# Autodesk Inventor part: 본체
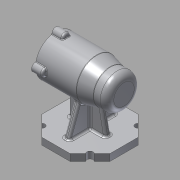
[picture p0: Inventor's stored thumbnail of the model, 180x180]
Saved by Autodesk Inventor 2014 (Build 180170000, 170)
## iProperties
Created: 2021-01
Part Number: 본체
Material: Aluminum 6061
Document SubType Name: Modeling
Designer: kh
Mass: 632.295 g
Surface Area: 613.777 cm^2
Volume: 233.319 cm^3
Density: 2.71 g/cm^3
Appearance: Aluminum - Flat
Author: kh
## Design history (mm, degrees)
sketch "Sketch1"
  geometry: L1 (20.711, 50)-(50, 20.711); L2 (50, 20.711)-(50, -20.711); L3 (50, -20.711)-(20.711, -50); L4 (20.711, -50)-(-20.711, -50); L5 (-20.711, -50)-(-50, -20.711); L6 (-50, -20.711)-(-50, 20.711); L7 (-50, 20.711)-(-20.711, 50); L8 (-20.711, 50)-(20.711, 50); L9 (0, 0)-(-35.355, 35.355); L10 (0, 0)-(-35.609, 0); L11 (0, 0)-(0, 25.422); C1 r 4.5 at (-35.355, 35.355); C2 r 4.5 at (35.355, 35.355); C3 r 4.5 at (-35.355, -35.355); C4 r 4.5 at (35.355, -35.355); A1 r 50 centre (0, 0) between (0, 50) and (-35.355, 35.355); 2 further points
  constraints: 22 end point, 5 centre point, 3 coincident, 3 midpoint, 3 symmetric about line, 2 point on circle, 1 horizontal alignment, 1 parallel, 1 perpendicular, 20 other
  dimensions: "d0" = 100 diameter of A1; "d1" = 9 diameter of C1
extrude "Extrusion1" new body sketch "Sketch1" distance "d2" = 10; taper "d3" = 0 deg
extrude "Extrusion2" cut sketch "Sketch1" stored distance "d4" = 10; taper "d5" = 0 deg
sketch "Sketch2"
  geometry: L1 (-50, 75)-(50, 75); L2 (-50, 75)-(-50, 100); L3 (-10, 105)-(50, 105); L4 (50, 105)-(50, 75); L5 (-50, 100)-(-30, 100); L6 (-30, 100)-(-10, 105); L7 (-44, 75)-(-44, 85.5); L8 (-44, 85.5)-(-41, 85.5); L9 (-41, 85.5)-(-41, 91); L10 (-41, 91)-(-37, 91); L11 (-37, 91)-(-37, 92.5); L12 (-37, 92.5)-(-19, 92.5); L13 (-19, 92.5)-(-19, 96); L14 (-19, 96)-(-7, 96); L15 (-7, 96)-(-7, 99); L16 (-7, 99)-(35, 99); L17 (35, 99)-(35, 96); L18 (35, 96)-(50, 96); L19 (-38.537, 10)-(-50, 10) reference; L20 (-27, 10)-(-23.809, 26.419); L21 (50, 10)-(38.537, 10) reference; L22 (27, 10)-(27, 23.538); 2 further points
  constraints: 40 end point, 11 perpendicular, 6 parallel, 4 point on line, 1 collinear, 1 horizontal, 1 midpoint, 1 vertical alignment
  dimensions: "d6" = 75 distance from line of L1 point (0, 0); "d7" = 100 distance of L1.start L1.end; "d8" = 60 diameter of L3 L1; "d9" = 50 diameter of L5 L1; "d10" = 20 distance of L2.end L5.end; "d11" = 40 horizontal distance of L2.end L3.start; "d12" = 42 diameter of L18 L1; "d13" = 48 diameter of L16 L1; "d14" = 35 diameter of L12 L1; "d15" = 32 diameter of L10 L1; "d16" = 21 diameter of L8 L1; "d17" = 15 distance of L17.end L18.end; "d18" = 42 distance of L15.end L16.end; "d19" = 12 distance of L13.end L14.end; "d20" = 18 distance of L11.end L12.end; "d21" = 3 distance of L7.end L8.end; "d22" = 4 distance of L9.end L10.end; "d24" = 23 distance of L19.end L20.start; "d25" = 101 deg angle of L19 L20; "d26" = 23 distance of L21.start L22.start
revolve "Revolution1" stored, may be unused: angle "d23" = 90 deg
feature "Rib1" dims "d27" = 1, "d28" = 8, "d29" = 0, "d30" = 0, "d31" = 1, "d32" = 1
feature "Rib2" dims "d33" = 1, "d34" = 8, "d35" = 0, "d36" = 0, "d37" = 1, "d38" = 1
sketch "Sketch3"
  geometry: L1 (38.537, 10)-(50, 10) reference; L2 (35, 10)-(27.971, 29.311); L3 (0, 0)-(0, -18.944); L4 (-35, 10)-(-27.971, 29.311)
  constraints: 6 end point, 2 symmetric about line, 1 perpendicular, 1 point on line
  dimensions: "d39" = 15 distance of L1.end L2.start; "d40" = 110 deg angle of L1 L2
feature "Rib3" dims "d41" = 1, "d42" = 8, "d43" = 0, "d44" = 0, "d45" = 1, "d46" = 1
feature "Rib4" dims "d47" = 1, "d48" = 8, "d49" = 0, "d50" = 0, "d51" = 1, "d52" = 1
sketch "Sketch4"
  geometry: L1 (0, 0)-(30, 0); C1 r 6 at (30, 0); 1 further point
  constraints: 2 end point, 1 centre point, 1 coincident, 1 horizontal, 1 horizontal alignment, 1 other
  dimensions: "d53" = 12 diameter of C1
extrude "Extrusion3" join sketch "Sketch4" distance "d54" = 16; taper "d55" = 0 deg
hole "Hole1" diameter "d58" = 3.242; stored, may be unused: countersink angle "d62" = 90 deg, drill point angle "d64" = 118 deg; dims "d56" = 10, "d57" = 10, "d59" = 8, "d60" = 4, "d61" = 2, "d63" = 10
fillet "Fillet1" dims "d65" = 1, "d66" = 3, "d71" = 10
pattern_circular "Circular Pattern1" dims "d68" = 360 deg
fillet "Fillet2" dims "d70" = 3
chamfer "Chamfer1" distance "d72" = 1; stored, may be unused: second distance "d73" = 2, angle "d74" = 45 deg
fillet "Fillet3" dims "d75" = 3, "d76" = 0.3
workplane "Work Plane1"
sketch "Sketch5"
  geometry: L1 (-70, -15)-(-70, 15) reference; L2 (-70, 0)-(48.153, 0); L3 (-66.354, 2.402)-(50.354, 2.402); L4 (50.354, 2.402)-(50.354, -2.402); L5 (50.354, -2.402)-(-66.354, -2.402); L6 (-66.354, -2.402)-(-66.354, 2.402); L7 (-66.354, 0)-(50.354, 0); L8 (-8, 2.402)-(-8, -2.402); L9 (30, 6.771)-(30, 29.226) reference; 2 further points
  constraints: 6 end point, 6 midpoint, 1 perpendicular, 1 point on line, 2 other
  dimensions: "d77" = 38 distance between parallel lines of L9 L8
emboss "Emboss1" sketch "Sketch5" dims "d0" = 100, "d1" = 9, "d78" = 0.5, "d79" = 0
body "Solid1"
